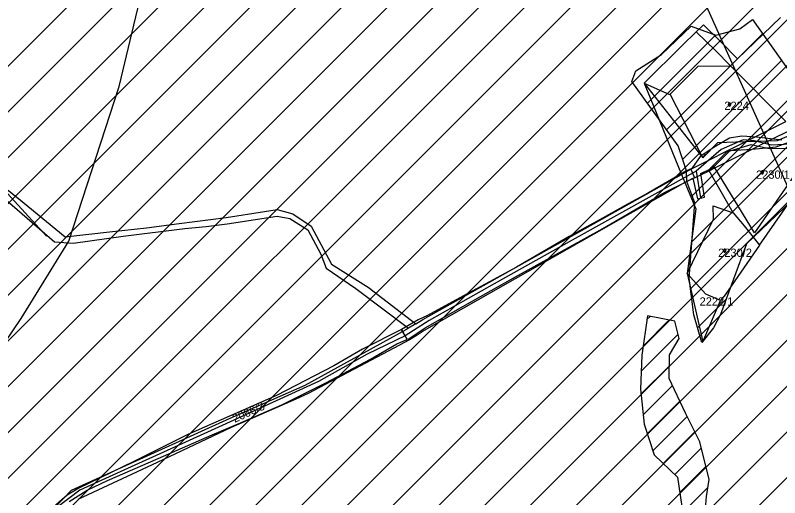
# Model space of a CAD drawing. Extents: x -564810 to -550519, y -1045831 to -1034011.
# Drawn here: x -552473.2 to -552001, y -1038084.6 to -1037786.6 of the extents above; entities that cross this region are included whole.
import ezdxf

# ---------------------------------------------------------------- set-up
doc = ezdxf.new("R2010")
doc.units = 0
for name, color, linetype in [('Interakční prvky', 7, 'Continuous'), ('KN stav', 7, 'Continuous'), ('Lesní porost', 7, 'Continuous'), ('Parcelní čísla', 7, 'Continuous'), ('přeložka st silnice', 7, 'Continuous'), ('STG', 7, 'Continuous'), ('vodní toky', 7, 'Continuous'), ('Vrstva 14', 7, 'Continuous'), ('Vrstva 33', 7, 'Continuous'), ('Vrstva 4', 7, 'Continuous'), ('zamokř ploch', 7, 'Continuous')]:
    doc.layers.add(name, color=color, linetype=linetype)

msp = doc.modelspace()

# ---------------------------------------------------------------- linework, layer by layer
at = {"layer": 'Interakční prvky'}
msp.add_lwpolyline([(-552827.49, -1037538.7), (-552658.27, -1037699.45), (-552453.79, -1037922.94)], dxfattribs=at)
at = {"layer": 'KN stav'}
for p, q in [((-552000.45, -1037787.9), (-552027.11, -1037813.53)), ((-552052.5, -1037796.76), (-552061.04, -1037805.09)), ((-552048.08, -1037792.46), (-552052.5, -1037796.76)), ((-552052.5, -1037796.76), (-552040.41, -1037808.62)), ((-552037.74, -1037802.66), (-552048.08, -1037792.46)), ((-552061.04, -1037805.09), (-552084.62, -1037828.63)), ((-552027.11, -1037813.53), (-552037.74, -1037802.66)), ((-552040.41, -1037808.62), (-552031.42, -1037817.84)), ((-552068.72, -1037835.26), (-552051.26, -1037818.03)), ((-552051.26, -1037818.03), (-552031.42, -1037817.84)), ((-552031.42, -1037817.84), (-551997.24, -1037852.29)), ((-552084.62, -1037828.63), (-552061.61, -1037884.92)), ((-552048.56, -1037874.57), (-552068.72, -1037835.26)), ((-552003.23, -1037867.88), (-551987.76, -1037862.05)), ((-551990.66, -1037858.92), (-552002.53, -1037864.19)), ((-552039.45, -1037865.34), (-552048.56, -1037874.57)), ((-552022.3, -1037864.81), (-552039.45, -1037865.34)), ((-552008.3, -1037864.37), (-552022.3, -1037864.81)), ((-552002.53, -1037864.19), (-552008.3, -1037864.37)), ((-552041.4, -1037880.11), (-552031.64, -1037870.15)), ((-552031.64, -1037870.15), (-552018.03, -1037869.25)), ((-552018.03, -1037869.25), (-552003.23, -1037867.88)), ((-551981.03, -1037869.33), (-552016.59, -1037920.96)), ((-552061.61, -1037884.92), (-552055.85, -1037881.56)), ((-552055.85, -1037881.56), (-552053.59, -1037887.1)), ((-552041.4, -1037880.11), (-552044.61, -1037882.59)), ((-552040.99, -1037880.78), (-552041.4, -1037880.11)), ((-552016.59, -1037920.96), (-552040.99, -1037880.78)), ((-552491.07, -1037883.96), (-552471.14, -1037899.85)), ((-552221.44, -1037974.51), (-552061.61, -1037884.92)), ((-552013.44, -1037928.59), (-551980.89, -1037881.8)), ((-552059.56, -1037889.94), (-552220.66, -1037981.33)), ((-552053.59, -1037887.1), (-552059.56, -1037889.94)), ((-552059.56, -1037889.94), (-552052.71, -1037906.24)), ((-552471.14, -1037899.85), (-552442.33, -1037923.43)), ((-552478.09, -1037901.31), (-552448.95, -1037926.48)), ((-552041.93, -1037912.46), (-552042.02, -1037904.38)), ((-552042.02, -1037904.38), (-552029.75, -1037908.59)), ((-552342.89, -1037911.57), (-552319.17, -1037907.87)), ((-552319.17, -1037907.87), (-552311.44, -1037906.66)), ((-552311.44, -1037906.66), (-552301.64, -1037909.31)), ((-552301.64, -1037909.31), (-552290.32, -1037916.86)), ((-552052.71, -1037906.24), (-552058.22, -1037946.01)), ((-552029.75, -1037908.59), (-552022.83, -1037916.57)), ((-552371.96, -1037915.21), (-552342.89, -1037911.57)), ((-552342.3, -1037915.41), (-552311.37, -1037910.77)), ((-552311.37, -1037910.77), (-552303.5, -1037912.09)), ((-552303.5, -1037912.09), (-552292.51, -1037919.18)), ((-552058.22, -1037946.01), (-552041.93, -1037912.46)), ((-552414.99, -1037920.31), (-552392.08, -1037917.99)), ((-552406.45, -1037922.96), (-552368.45, -1037918.32)), ((-552392.08, -1037917.99), (-552371.96, -1037915.21)), ((-552368.45, -1037918.32), (-552355.34, -1037917.13)), ((-552355.34, -1037917.13), (-552342.3, -1037915.41)), ((-552292.51, -1037919.18), (-552284.43, -1037934.22)), ((-552290.32, -1037916.86), (-552277.91, -1037940.41)), ((-552022.83, -1037916.57), (-552013.44, -1037928.59)), ((-552442.33, -1037923.43), (-552414.99, -1037920.31)), ((-552437.43, -1037927.27), (-552406.45, -1037922.96)), ((-552448.95, -1037926.48), (-552437.43, -1037927.27)), ((-552013.44, -1037928.59), (-552034.73, -1037959.18)), ((-552284.43, -1037934.22), (-552281.16, -1037942.73)), ((-552281.16, -1037942.73), (-552262.71, -1037955.35)), ((-552277.91, -1037940.41), (-552254.64, -1037954.88)), ((-552046.56, -1037958.93), (-552058.22, -1037946.01)), ((-552058.22, -1037946.01), (-552048.45, -1037988.33)), ((-552262.71, -1037955.35), (-552230.17, -1037979.85)), ((-552254.64, -1037954.88), (-552252.2, -1037956.77)), ((-552252.2, -1037956.77), (-552225.81, -1037977.18)), ((-552037.52, -1037962.71), (-552046.56, -1037958.93)), ((-552034.73, -1037959.18), (-552037.52, -1037962.71)), ((-552048.45, -1037988.33), (-552037.52, -1037962.71)), ((-552225.81, -1037977.18), (-552221.44, -1037974.51)), ((-552231.86, -1037980.88), (-552294.2, -1038015.37)), ((-552230.17, -1037979.85), (-552231.86, -1037980.88)), ((-552225.81, -1037977.18), (-552230.17, -1037979.85)), ((-552224.88, -1037984.12), (-552229.63, -1037987.12)), ((-552220.66, -1037981.33), (-552224.88, -1037984.12)), ((-552229.63, -1037987.12), (-552239.33, -1037992.26)), ((-552239.33, -1037992.26), (-552292.32, -1038020.31)), ((-552294.2, -1038015.37), (-552340.56, -1038035.61)), ((-552292.32, -1038020.31), (-552299.94, -1038023.68)), ((-552299.94, -1038023.68), (-552339.74, -1038041.26)), ((-552340.56, -1038035.61), (-552438.66, -1038080.22)), ((-552339.74, -1038041.26), (-552385.53, -1038062.75)), ((-552385.53, -1038062.75), (-552434.54, -1038085.75)), ((-552438.66, -1038080.22), (-552468.77, -1038111.06))]:
    msp.add_line(p, q, dxfattribs=at)
at = {"layer": 'Lesní porost'}
for p, q in [((-552082.67, -1037840.83), (-552040.63, -1037798.79)), ((-552070.82, -1037857.26), (-552011.63, -1037798.07)), ((-552060.84, -1037875.57), (-551999.87, -1037814.59)), ((-552055.03, -1037898.04), (-551988.11, -1037831.12)), ((-552055.19, -1037926.49), (-551976.36, -1037847.65)), ((-552056.08, -1037955.66), (-551966.8, -1037866.38)), ((-552051.77, -1037979.63), (-552034.06, -1037961.92))]:
    msp.add_line(p, q, dxfattribs=at)
msp.add_lwpolyline([(-551984.54, -1037892.61), (-552021.45, -1037927.82), (-552037.56, -1037971.39), (-552041.86, -1037979.7), (-552049.14, -1037988.78), (-552054.1, -1037971.55), (-552056.91, -1037949.04), (-552053.36, -1037902.38), (-552058.43, -1037889.25), (-552058.47, -1037882.68), (-552063.62, -1037867.23), (-552092.24, -1037827.56), (-552089.82, -1037820.93), (-552073.96, -1037810.85), (-552055.74, -1037793.23), (-552040.41, -1037798.87), (-552025.52, -1037794.88), (-552017.87, -1037789.29), (-551972.11, -1037853.62)], dxfattribs=at)
at = {"layer": 'přeložka st silnice'}
for p, q in [((-552672.27, -1038069.15), (-552074.48, -1037471.35)), ((-552684.33, -1038109.49), (-552060.22, -1037485.38)), ((-552696.39, -1038149.84), (-552045.96, -1037499.4)), ((-552741.55, -1038223.28), (-552031.7, -1037513.43)), ((-552648.15, -1037988.46), (-552225.68, -1037565.99)), ((-552660.21, -1038028.8), (-552212.53, -1037581.12)), ((-552921.51, -1038431.52), (-552096.65, -1037606.66)), ((-553031.34, -1038795.91), (-551867.4, -1037631.97)), ((-553022.09, -1038814.94), (-551848.97, -1037641.83)), ((-552948.43, -1038486.73), (-552115.14, -1037653.44)), ((-553012.83, -1038833.97), (-551835.65, -1037656.79)), ((-552975.36, -1038541.94), (-552096.2, -1037662.78)), ((-553003.58, -1038853), (-551822.33, -1037671.75)), ((-552994.16, -1038589.02), (-552077.26, -1037672.13)), ((-553000.57, -1038623.72), (-552058.32, -1037681.47)), ((-553006.98, -1038658.42), (-552039.38, -1037690.81)), ((-553013.4, -1038693.11), (-552020.44, -1037700.16)), ((-553019.81, -1038727.81), (-552001.5, -1037709.5)), ((-553026.22, -1038762.51), (-551982.56, -1037718.84)), ((-552988.3, -1038866.01), (-551899.29, -1037777)), ((-552896.76, -1038802.75), (-551890.75, -1037796.74)), ((-552878.46, -1038812.73), (-551882.2, -1037816.47)), ((-552860.16, -1038822.72), (-551871.31, -1037833.87)), ((-552448.84, -1038439.68), (-551855.43, -1037846.27)), ((-552433.95, -1038453.08), (-551839.54, -1037858.67)), ((-552419.07, -1038466.48), (-551823.65, -1037871.07)), ((-552404.19, -1038479.88), (-551807.77, -1037883.46))]:
    msp.add_line(p, q, dxfattribs=at)
at = {"layer": 'STG'}
for points in [[(-552408.94, -1037830.61), (-552375.87, -1037691.87), (-552360.25, -1037612.86), (-552349.23, -1037577.94), (-552321.67, -1037544.87), (-552272.99, -1037500.76), (-552208.69, -1037463.09), (-552160.93, -1037413.48), (-552004.78, -1037243.5), (-551961.6, -1037184.7)], [(-552738.7, -1038346.98), (-552708.38, -1038265.2), (-552690.01, -1038230.29), (-552643.17, -1038169.65), (-552598.16, -1038120.95), (-552554.07, -1038074.09), (-552498.95, -1038017.13), (-552469.56, -1037973.94), (-552440.17, -1037926.17), (-552408.94, -1037830.61)]]:
    msp.add_lwpolyline(points, dxfattribs=at)
at = {"layer": 'vodní toky'}
for p, q in [((-552231.09, -1037986.94), (-552232.37, -1037984.68)), ((-552253.78, -1037999.03), (-552237.51, -1037989.57)), ((-552237.51, -1037989.57), (-552231.09, -1037986.94)), ((-552281.27, -1038013.68), (-552253.78, -1037999.03)), ((-552276.47, -1038003.12), (-552311.79, -1038021.45)), ((-552308.47, -1038027.24), (-552281.27, -1038013.68)), ((-552311.79, -1038021.45), (-552366.67, -1038045.55)), ((-552333.96, -1038038.29), (-552308.47, -1038027.24)), ((-552351.52, -1038045.8), (-552333.96, -1038038.29)), ((-552366.67, -1038045.55), (-552400.4, -1038062.37)), ((-552384.89, -1038060.39), (-552351.52, -1038045.8)), ((-552366.67, -1038045.55), (-552366.67, -1038045.55)), ((-552416.29, -1038073.97), (-552384.89, -1038060.39)), ((-552400.4, -1038062.37), (-552433.82, -1038078.66)), ((-552428.7, -1038080.02), (-552416.29, -1038073.97)), ((-552433.82, -1038078.66), (-552441.08, -1038083)), ((-552439.79, -1038086.97), (-552428.7, -1038080.02)), ((-552441.08, -1038083), (-552449.43, -1038090.15))]:
    msp.add_line(p, q, dxfattribs=at)
for points in [[(-551999.66, -1037863.72), (-552015.37, -1037861.86), (-552024.35, -1037861.34), (-552031.92, -1037862.56), (-552041.05, -1037867.89), (-552050.17, -1037873.84), (-552055.19, -1037881.33), (-552058.47, -1037882.68), (-552082, -1037896.25), (-552094.49, -1037902.99), (-552111.95, -1037912.83), (-552131.12, -1037923.22), (-552163.58, -1037942.21), (-552180.22, -1037951.26), (-552196.26, -1037959.84), (-552218.5, -1037972.01), (-552224.25, -1037974.68), (-552234.66, -1037980.64), (-552231.09, -1037986.94)], [(-552230.5, -1037986.68), (-552219.89, -1037979.69), (-552185.88, -1037960.26), (-552164.18, -1037948.15), (-552110.3, -1037918.33), (-552083.02, -1037902.48), (-552072.08, -1037896.01), (-552058.43, -1037889.25), (-552054.7, -1037887.16), (-552051.83, -1037900.06), (-552047.35, -1037899.03), (-552049.64, -1037884.27), (-552044.45, -1037881.82), (-552033.69, -1037870.94), (-552018.66, -1037866.43), (-552007.39, -1037868.93), (-551986.81, -1037868.69)], [(-552232.37, -1037984.68), (-552234.66, -1037980.64), (-552258.71, -1037992.81), (-552276.47, -1038003.12)]]:
    msp.add_lwpolyline(points, dxfattribs=at)
at = {"layer": 'Vrstva 14'}
msp.add_lwpolyline([(-551754.89, -1038428.38), (-553519.59, -1034507.17), (-553502.09, -1034572.44)], dxfattribs=at)
at = {"layer": 'Vrstva 33'}
msp.add_line((-552052.56, -1037882.93), (-552049.83, -1037899.42), dxfattribs=at)
msp.add_lwpolyline([(-551986.23, -1037865.71), (-552006.06, -1037866.84), (-552016.66, -1037864.12), (-552023.6, -1037863.53), (-552037.07, -1037869.55), (-552052.56, -1037882.93), (-552129.26, -1037925.56), (-552177.43, -1037952.58), (-552217.56, -1037975.08), (-552232.35, -1037984.67), (-552255.9, -1037995.85), (-552285.83, -1038012.72), (-552347.6, -1038040.98), (-552433.27, -1038079.94), (-552447.63, -1038090.75), (-552493.86, -1038145.85), (-552529.51, -1038188.84), (-552553.7, -1038218.28), (-552572.24, -1038240.64), (-552601.99, -1038276.21), (-552654.87, -1038312.34), (-552739.97, -1038410.7)], dxfattribs=at)
at = {"layer": 'Vrstva 4'}
for p, q in [((-552031.42, -1037817.84), (-552027.11, -1037813.53)), ((-552084.62, -1037828.63), (-552069.01, -1037835.52)), ((-552084.62, -1037828.63), (-552048.56, -1037874.57)), ((-552022.3, -1037864.8), (-551997.24, -1037852.29)), ((-552008.3, -1037864.37), (-551992.92, -1037856.64)), ((-552055.85, -1037881.56), (-552022.3, -1037864.8)), ((-552018.03, -1037869.25), (-552008.3, -1037864.37)), ((-552040.99, -1037880.77), (-552018.03, -1037869.25)), ((-552048.56, -1037874.57), (-552046.61, -1037872.41)), ((-552044.61, -1037882.59), (-552040.99, -1037880.78)), ((-552061.61, -1037884.92), (-552059.56, -1037889.94)), ((-552053.59, -1037887.1), (-552044.61, -1037882.59)), ((-552029.75, -1037908.59), (-552044.61, -1037882.59))]:
    msp.add_line(p, q, dxfattribs=at)
at = {"layer": 'zamokř ploch'}
for p, q in [((-552032.96, -1037841.66), (-552030.96, -1037841.66)), ((-552032.46, -1037842.16), (-552032.46, -1037841.16)), ((-552031.46, -1037841.16), (-552031.46, -1037842.16)), ((-552012.68, -1037883.61), (-552010.68, -1037883.61)), ((-552012.18, -1037884.11), (-552012.18, -1037883.11)), ((-552011.18, -1037883.11), (-552011.18, -1037884.11)), ((-552036.02, -1037932.01), (-552034.02, -1037932.01)), ((-552035.52, -1037932.51), (-552035.52, -1037931.51)), ((-552034.52, -1037931.51), (-552034.52, -1037932.51)), ((-552082.74, -1037972.25), (-552086.18, -1037996.62)), ((-552085.39, -1037991.01), (-552069.19, -1037974.81)), ((-552083.06, -1037974.54), (-552081.08, -1037972.56)), ((-552065.76, -1037975.46), (-552082.74, -1037972.25)), ((-552063.07, -1037986.24), (-552065.76, -1037975.46)), ((-552086.58, -1038006.34), (-552063.75, -1037983.51)), ((-552069.02, -1037996.38), (-552063.07, -1037986.24)), ((-552086.18, -1037996.62), (-552087.03, -1038017.49)), ((-552069.31, -1038010.88), (-552069.02, -1037996.38)), ((-552086.71, -1038020.61), (-552069.15, -1038003.06)), ((-552059.25, -1038032.42), (-552069.31, -1038010.88)), ((-552087.03, -1038017.49), (-552084.78, -1038039.19)), ((-552085.38, -1038033.42), (-552067.25, -1038015.3)), ((-552082.86, -1038045.05), (-552062.75, -1038024.94)), ((-552050.4, -1038050.15), (-552059.25, -1038032.42)), ((-552079.36, -1038055.69), (-552058.2, -1038034.53)), ((-552084.78, -1038039.19), (-552078.57, -1038058.1)), ((-552072.97, -1038063.44), (-552053.49, -1038043.96)), ((-552044.47, -1038073.26), (-552050.4, -1038050.15)), ((-552065.72, -1038070.34), (-552049.41, -1038054.02)), ((-552078.57, -1038058.1), (-552064.04, -1038071.94)), ((-552062.71, -1038081.47), (-552046.52, -1038065.28)), ((-552064.04, -1038071.94), (-552061.52, -1038090.02)), ((-552046.27, -1038083.78), (-552044.47, -1038073.26)), ((-552064.38, -1038097.28), (-552045.32, -1038078.22)), ((-552047.09, -1038093.65), (-552046.27, -1038083.78))]:
    msp.add_line(p, q, dxfattribs=at)
for centre, start, end in [((-552031.96, -1037841.16), 0, 180), ((-552031.96, -1037842.16), 180, 0), ((-552011.68, -1037883.11), 0, 180), ((-552011.68, -1037884.11), 180, 0), ((-552035.02, -1037931.51), 0, 180), ((-552035.02, -1037932.51), 180, 0)]:
    msp.add_arc(centre, 0.5, start, end, dxfattribs=at)

# ---------------------------------------------------------------- texts
at = {"layer": 'Parcelní čísla'}
for s, p in [('2224', (-552035.18, -1037845.03)), ('2230/1', (-552015.59, -1037887.57)), ('2230/2', (-552039, -1037935.83)), ('2222/1', (-552050.46, -1037965.94))]:
    msp.add_text(s, height=5.1, dxfattribs=at).set_placement(p)
msp.add_text('2066/3', height=5.1, rotation=24.1615, dxfattribs=at).set_placement((-552337.58, -1038038.36))

doc.saveas('drawing.dxf')
